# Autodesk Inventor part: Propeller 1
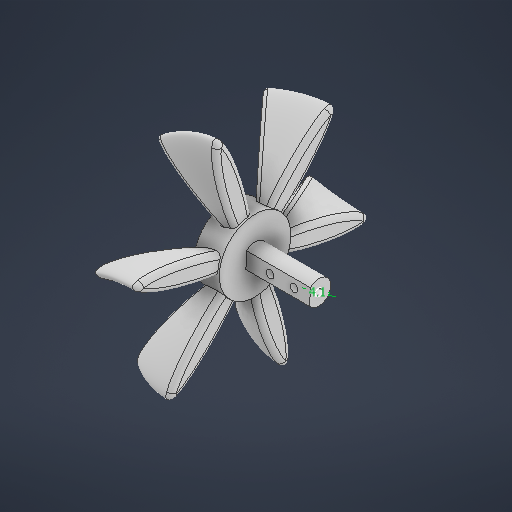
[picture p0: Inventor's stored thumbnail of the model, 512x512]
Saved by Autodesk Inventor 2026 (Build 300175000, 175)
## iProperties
Created: 2025-10
Part Number: Propeller 1
Material: Generic
Document SubType Name: Modeling
Designer: sab273
Density: 1 g/cm^3
Appearance: Default
Author: sab273
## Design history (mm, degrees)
sketch "Sketch1"
  geometry: L1 (0, 0)-(-69.651, 0); C1 r 100 at (0, 0); C2 r 7.27 at (-29.081, 27.465); 1 further point
  constraints: 2 centre point, 2 end point, 1 coincident, 1 horizontal
revolve "Revolution1" sketch "Sketch1" stored, may be unused: angle "d7" = 40 deg
fillet "Fillet1" dims "d8" = 3
fillet "Fillet2" dims "d9" = 2
sketch "3D Sketch1"
pattern_circular "Circular Pattern1" dims "d11" = 360 deg
sketch "Sketch2"
  geometry: C1 r 22.5 at (16.016, -36.36); 1 further point
  constraints: 1 centre point, 1 coincident
  dimensions: "d13" = 45 diameter of C1
extrude "Extrusion1" join sketch "Sketch2" distance "d14" = 1; taper "d16" = 0 deg; dims "d15" = 15, "d17" = 0
sketch "Sketch5"
  geometry: C1 r 7.5 at (0, 0); 1 further point
  constraints: 1 centre point, 1 coincident
  dimensions: "d24" = 15 diameter of C1
extrude "Extrusion4" join sketch "Sketch5" distance "d25" = 40; taper "d26" = 0 deg
sketch "Sketch7"
  geometry: 1 further point
sketch "Sketch8"
  geometry: C1 r 2.05 at (0, 0); 1 further point
  constraints: 1 centre point, 1 coincident
  dimensions: "d34" = 4.1 diameter of C1
sketch "Sketch9"
  geometry: C1 r 2.05 at (0, 0); 1 further point
  constraints: 1 centre point, 1 coincident
  dimensions: "d31" = 4.1 diameter of C1
extrude "Extrusion6" cut sketch "Sketch9" distance "d32" = 60; taper "d33" = 0 deg
sketch "Sketch10"
  geometry: L1 (-5.774, -4.786)-(-5.377, 5.228); A1 r 7.5 centre (0, 0) between (-5.774, -4.786) and (-5.377, 5.228) reference; A2 r 7.5 centre (0, 0) between (-5.774, -4.786) and (-7.494, 0.297)
  constraints: 6 point on circle, 2 end point, 1 centre point, 1 concentric
extrude "Extrusion7" cut sketch "Sketch10" distance "d35" = 40; taper "d36" = 0 deg
sketch "Sketch11"
  geometry: L1 (40, -12.511)-(40, 2.489) reference; C1 r 2.4 at (30, -5.011); C2 r 2.4 at (15, -5.011); 3 further points
  constraints: 2 centre point
extrude "Extrusion8" cut sketch "Sketch11" distance "d42" = 40; taper "d43" = 0 deg
sketch "Sketch12"
  geometry: 1 further point
body "Solid1"
